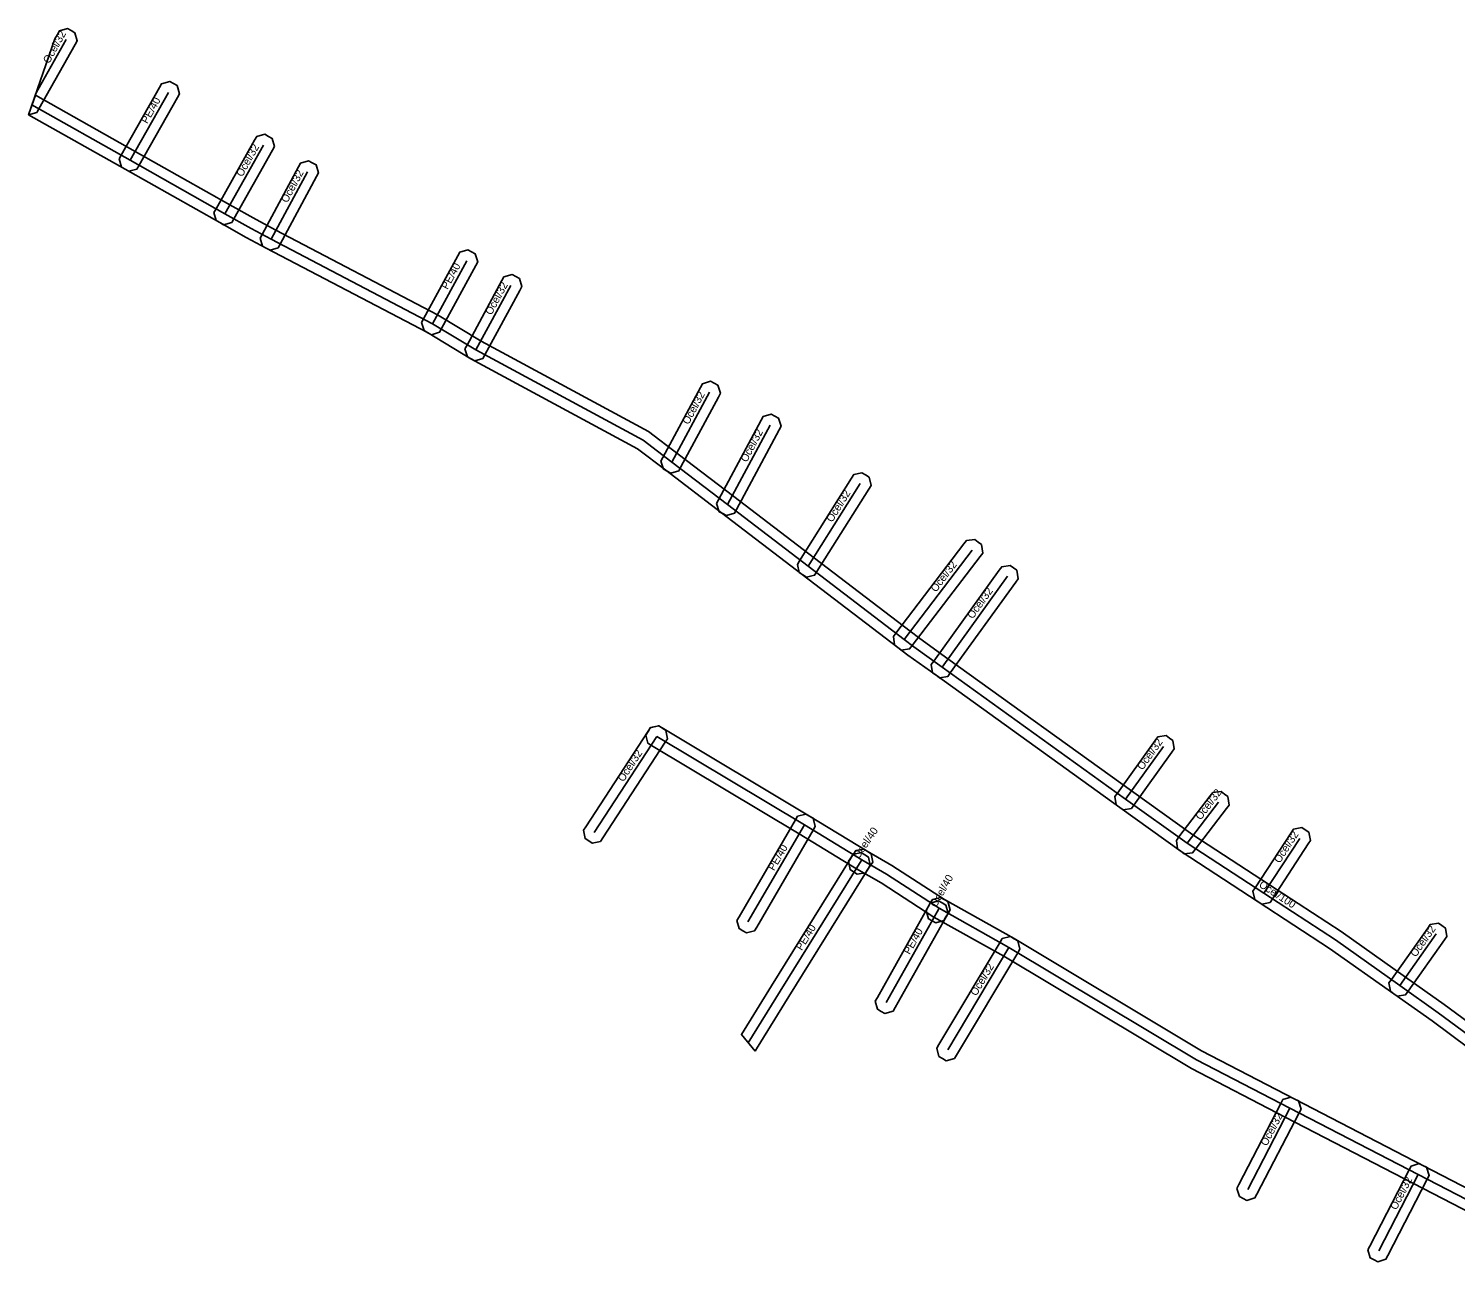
# Model space of a CAD drawing. Extents: x -588157 to -587884, y -1179022 to -1178805.
# Drawn here: x -588156.6 to -588016.9, y -1178925.9 to -1178805 of the extents above; entities that cross this region are included whole.
import ezdxf

# ---------------------------------------------------------------- set-up
doc = ezdxf.new("R2010")
doc.units = 0
for name, color, linetype in [('1', 7, 'Continuous'), ('14', 7, 'Continuous'), ('20', 7, 'Continuous')]:
    doc.layers.add(name, color=color, linetype=linetype)

msp = doc.modelspace()

# ---------------------------------------------------------------- linework, layer by layer
at = {"layer": '1'}
for points in [[(-588156.57, -1178813.424), (-588156.581, -1178813.418), (-588153.996, -1178805.976), (-588153.761, -1178805.559), (-588153.558, -1178805.198), (-588152.76, -1178804.976), (-588152.399, -1178805.179), (-588152.038, -1178805.382), (-588151.816, -1178806.18), (-588152.019, -1178806.541), (-588155.569, -1178812.841), (-588155.772, -1178813.202)], [(-588147.704, -1178817.75), (-588147.501, -1178817.389), (-588143.751, -1178810.739), (-588143.548, -1178810.378), (-588142.75, -1178810.156), (-588142.389, -1178810.359), (-588142.028, -1178810.562), (-588141.806, -1178811.36), (-588142.009, -1178811.721), (-588145.759, -1178818.371), (-588145.962, -1178818.732), (-588146.76, -1178818.954), (-588147.121, -1178818.751), (-588147.482, -1178818.548)], [(-588138.424, -1178822.98), (-588138.221, -1178822.619), (-588134.441, -1178815.919), (-588134.238, -1178815.558), (-588133.44, -1178815.336), (-588133.079, -1178815.539), (-588132.718, -1178815.742), (-588132.496, -1178816.54), (-588132.699, -1178816.901), (-588136.479, -1178823.601), (-588136.682, -1178823.962), (-588137.48, -1178824.184), (-588137.841, -1178823.981), (-588138.202, -1178823.778)], [(-588133.907, -1178825.501), (-588133.71, -1178825.136), (-588130.15, -1178818.526), (-588129.954, -1178818.161), (-588129.161, -1178817.923), (-588128.796, -1178818.12), (-588128.431, -1178818.316), (-588128.193, -1178819.109), (-588128.39, -1178819.474), (-588131.95, -1178826.084), (-588132.146, -1178826.449), (-588132.939, -1178826.687), (-588133.304, -1178826.49), (-588133.669, -1178826.294)], [(-588118.096, -1178833.768), (-588117.899, -1178833.404), (-588114.559, -1178827.234), (-588114.362, -1178826.87), (-588113.568, -1178826.634), (-588113.204, -1178826.831), (-588112.84, -1178827.028), (-588112.604, -1178827.822), (-588112.801, -1178828.186), (-588116.141, -1178834.356), (-588116.338, -1178834.72), (-588117.132, -1178834.956), (-588117.496, -1178834.759), (-588117.86, -1178834.562)], [(-588113.847, -1178836.338), (-588113.649, -1178835.973), (-588110.229, -1178829.663), (-588110.032, -1178829.299), (-588109.238, -1178829.063), (-588108.873, -1178829.261), (-588108.509, -1178829.458), (-588108.273, -1178830.252), (-588108.471, -1178830.617), (-588111.891, -1178836.927), (-588112.088, -1178837.291), (-588112.882, -1178837.527), (-588113.247, -1178837.329), (-588113.611, -1178837.132)], [(-588094.667, -1178847.333), (-588094.471, -1178846.968), (-588090.801, -1178840.118), (-588090.605, -1178839.753), (-588089.813, -1178839.513), (-588089.448, -1178839.709), (-588089.083, -1178839.905), (-588088.843, -1178840.697), (-588089.039, -1178841.062), (-588092.709, -1178847.912), (-588092.905, -1178848.277), (-588093.697, -1178848.517), (-588094.062, -1178848.321), (-588094.427, -1178848.125)], [(-588089.217, -1178851.494), (-588089.022, -1178851.129), (-588084.862, -1178843.339), (-588084.667, -1178842.974), (-588083.874, -1178842.733), (-588083.509, -1178842.928), (-588083.144, -1178843.123), (-588082.903, -1178843.916), (-588083.098, -1178844.281), (-588087.258, -1178852.071), (-588087.453, -1178852.436), (-588088.246, -1178852.677), (-588088.611, -1178852.482), (-588088.976, -1178852.287)], [(-588081.307, -1178857.449), (-588081.087, -1178857.098), (-588076.007, -1178849.008), (-588075.787, -1178848.657), (-588074.979, -1178848.473), (-588074.628, -1178848.693), (-588074.277, -1178848.913), (-588074.093, -1178849.721), (-588074.313, -1178850.072), (-588079.393, -1178858.162), (-588079.613, -1178858.513), (-588080.421, -1178858.697), (-588080.772, -1178858.477), (-588081.123, -1178858.257)], [(-588071.906, -1178864.513), (-588071.655, -1178864.183), (-588064.995, -1178855.453), (-588064.744, -1178855.124), (-588063.923, -1178855.014), (-588063.593, -1178855.265), (-588063.264, -1178855.516), (-588063.154, -1178856.337), (-588063.405, -1178856.667), (-588070.065, -1178865.397), (-588070.316, -1178865.726), (-588071.137, -1178865.836), (-588071.467, -1178865.585), (-588071.796, -1178865.334)], [(-588068.193, -1178867.252), (-588067.951, -1178866.916), (-588061.541, -1178858.016), (-588061.299, -1178857.68), (-588060.482, -1178857.547), (-588060.146, -1178857.789), (-588059.81, -1178858.031), (-588059.677, -1178858.848), (-588059.919, -1178859.184), (-588066.329, -1178868.084), (-588066.571, -1178868.42), (-588067.388, -1178868.553), (-588067.724, -1178868.311), (-588068.06, -1178868.069)], [(-588102.254, -1178883.49), (-588102.027, -1178883.143), (-588095.907, -1178873.773), (-588095.68, -1178873.426), (-588094.87, -1178873.256), (-588094.523, -1178873.483), (-588094.176, -1178873.71), (-588094.006, -1178874.52), (-588094.233, -1178874.867), (-588100.353, -1178884.237), (-588100.58, -1178884.584), (-588101.39, -1178884.754), (-588101.737, -1178884.527), (-588102.084, -1178884.3)], [(-588050.214, -1178880.182), (-588049.972, -1178879.846), (-588046.262, -1178874.686), (-588046.02, -1178874.35), (-588045.202, -1178874.216), (-588044.866, -1178874.458), (-588044.53, -1178874.7), (-588044.396, -1178875.518), (-588044.638, -1178875.854), (-588048.348, -1178881.014), (-588048.59, -1178881.35), (-588049.408, -1178881.484), (-588049.744, -1178881.242), (-588050.08, -1178881)], [(-588044.196, -1178884.472), (-588043.944, -1178884.143), (-588040.874, -1178880.127), (-588040.623, -1178879.798), (-588039.802, -1178879.688), (-588039.473, -1178879.94), (-588039.144, -1178880.191), (-588039.034, -1178881.012), (-588039.286, -1178881.341), (-588042.356, -1178885.357), (-588042.607, -1178885.686), (-588043.428, -1178885.796), (-588043.757, -1178885.544), (-588044.086, -1178885.293)], [(-588087.222, -1178892.315), (-588087.014, -1178891.957), (-588081.484, -1178882.467), (-588081.276, -1178882.109), (-588080.475, -1178881.898), (-588080.117, -1178882.106), (-588079.759, -1178882.314), (-588079.548, -1178883.115), (-588079.756, -1178883.473), (-588085.286, -1178892.963), (-588085.494, -1178893.321), (-588086.295, -1178893.532), (-588086.653, -1178893.324), (-588087.011, -1178893.116)], [(-588036.694, -1178889.461), (-588036.468, -1178889.114), (-588032.958, -1178883.734), (-588032.731, -1178883.387), (-588031.921, -1178883.216), (-588031.574, -1178883.442), (-588031.227, -1178883.669), (-588031.056, -1178884.479), (-588031.282, -1178884.826), (-588034.792, -1178890.206), (-588035.019, -1178890.553), (-588035.829, -1178890.724), (-588036.176, -1178890.498), (-588036.523, -1178890.271)], [(-588073.931, -1178886.614), (-588074.165, -1178886.956), (-588074.405, -1178887.306), (-588074.639, -1178887.647), (-588075.454, -1178887.799), (-588075.796, -1178887.565), (-588076.137, -1178887.331), (-588076.289, -1178886.516), (-588076.055, -1178886.174), (-588075.815, -1178885.824), (-588075.581, -1178885.483), (-588074.766, -1178885.331), (-588074.424, -1178885.565), (-588074.083, -1178885.799)], [(-588085.452, -1178905.119), (-588086.79, -1178903.484), (-588083.84, -1178898.723), (-588076.08, -1178886.213), (-588075.862, -1178885.861), (-588075.055, -1178885.672), (-588074.703, -1178885.89), (-588074.351, -1178886.108), (-588074.162, -1178886.915), (-588074.38, -1178887.267), (-588082.14, -1178899.777), (-588085.301, -1178904.878), (-588085.352, -1178904.96)], [(-588073.675, -1178900.221), (-588073.472, -1178899.86), (-588068.492, -1178890.99), (-588068.289, -1178890.629), (-588067.491, -1178890.405), (-588067.13, -1178890.608), (-588066.769, -1178890.811), (-588066.545, -1178891.609), (-588066.748, -1178891.97), (-588071.728, -1178900.84), (-588071.931, -1178901.201), (-588072.729, -1178901.425), (-588073.09, -1178901.222), (-588073.451, -1178901.019)], [(-588068.693, -1178891.344), (-588068.488, -1178890.984), (-588068.288, -1178890.634), (-588068.083, -1178890.274), (-588067.284, -1178890.057), (-588066.924, -1178890.262), (-588066.564, -1178890.467), (-588066.347, -1178891.266), (-588066.552, -1178891.626), (-588066.752, -1178891.976), (-588066.957, -1178892.336), (-588067.756, -1178892.553), (-588068.116, -1178892.348), (-588068.476, -1178892.143)], [(-588023.386, -1178898.441), (-588023.147, -1178898.103), (-588019.587, -1178893.063), (-588019.348, -1178892.725), (-588018.531, -1178892.584), (-588018.193, -1178892.823), (-588017.855, -1178893.062), (-588017.714, -1178893.879), (-588017.953, -1178894.217), (-588021.513, -1178899.257), (-588021.752, -1178899.595), (-588022.569, -1178899.736), (-588022.907, -1178899.497), (-588023.245, -1178899.258)], [(-588067.65, -1178904.822), (-588067.438, -1178904.467), (-588061.448, -1178894.447), (-588061.236, -1178894.092), (-588060.432, -1178893.89), (-588060.077, -1178894.102), (-588059.722, -1178894.314), (-588059.52, -1178895.118), (-588059.732, -1178895.473), (-588065.722, -1178905.493), (-588065.934, -1178905.848), (-588066.738, -1178906.05), (-588067.093, -1178905.838), (-588067.448, -1178905.626)], [(-588038.279, -1178918.557), (-588038.088, -1178918.189), (-588033.958, -1178910.229), (-588033.767, -1178909.862), (-588032.977, -1178909.611), (-588032.609, -1178909.802), (-588032.242, -1178909.993), (-588031.991, -1178910.783), (-588032.182, -1178911.151), (-588036.312, -1178919.111), (-588036.503, -1178919.478), (-588037.293, -1178919.729), (-588037.661, -1178919.538), (-588038.028, -1178919.347)], [(-588025.458, -1178924.569), (-588025.268, -1178924.201), (-588021.408, -1178916.731), (-588021.218, -1178916.363), (-588020.429, -1178916.112), (-588020.061, -1178916.302), (-588019.693, -1178916.492), (-588019.442, -1178917.281), (-588019.632, -1178917.649), (-588023.492, -1178925.119), (-588023.682, -1178925.487), (-588024.471, -1178925.738), (-588024.839, -1178925.548), (-588025.207, -1178925.358)]]:
    msp.add_lwpolyline(points, close=True, dxfattribs=at)
for points in [[(-588015.544, -1178904.832), (-588019.14, -1178902.163), (-588022.907, -1178899.497), (-588029.192, -1178895.057), (-588036.177, -1178890.497), (-588043.715, -1178885.575), (-588049.744, -1178881.242), (-588067.723, -1178868.312), (-588070.494, -1178866.324), (-588071.466, -1178865.585), (-588080.847, -1178858.425), (-588088.747, -1178852.395), (-588094.197, -1178848.235), (-588096.954, -1178846.133), (-588113.267, -1178837.318), (-588117.511, -1178834.752), (-588133.299, -1178826.493), (-588135.263, -1178825.436), (-588137.841, -1178823.981), (-588147.121, -1178818.751), (-588156.581, -1178813.418), (-588155.914, -1178811.499), (-588146.139, -1178817.009), (-588136.859, -1178822.239), (-588134.297, -1178823.684), (-588132.361, -1178824.727), (-588116.529, -1178833.008), (-588112.273, -1178835.582), (-588095.866, -1178844.447), (-588092.983, -1178846.645), (-588087.533, -1178850.805), (-588079.633, -1178856.835), (-588070.254, -1178863.995), (-588069.306, -1178864.716), (-588066.557, -1178866.688), (-588048.576, -1178879.618), (-588042.585, -1178883.925), (-588035.083, -1178888.823), (-588028.068, -1178893.403), (-588021.753, -1178897.863), (-588017.966, -1178900.543), (-588014.376, -1178903.208)], [(-588005.841, -1178925.907), (-588020.98, -1178918.078), (-588033.53, -1178911.578), (-588042.717, -1178906.824), (-588061.091, -1178895.825), (-588067.937, -1178891.987), (-588073.113, -1178888.633), (-588075.5, -1178887.25), (-588081.136, -1178883.826), (-588095.584, -1178875.178), (-588095.939, -1178874.965), (-588096.141, -1178874.161), (-588095.928, -1178873.806), (-588095.715, -1178873.451), (-588094.911, -1178873.249), (-588094.556, -1178873.462), (-588080.104, -1178882.114), (-588074.48, -1178885.53), (-588072.067, -1178886.927), (-588066.903, -1178890.273), (-588060.089, -1178894.095), (-588041.743, -1178905.076), (-588032.61, -1178909.802), (-588020.06, -1178916.302), (-588004.919, -1178924.133)]]:
    msp.add_lwpolyline(points, dxfattribs=at)
at = {"layer": '14'}
for points in [[(-588155.84, -1178811.286), (-588152.89, -1178806.05)], [(-588146.63, -1178817.88), (-588142.88, -1178811.23)], [(-588014.96, -1178904.02), (-588018.553, -1178901.353), (-588022.33, -1178898.68), (-588028.63, -1178894.23), (-588035.63, -1178889.66), (-588043.15, -1178884.75), (-588049.16, -1178880.43), (-588067.14, -1178867.5), (-588069.9, -1178865.52), (-588070.86, -1178864.79), (-588080.24, -1178857.63), (-588088.14, -1178851.6), (-588093.59, -1178847.44), (-588096.41, -1178845.29), (-588112.77, -1178836.45), (-588117.02, -1178833.88), (-588132.83, -1178825.61), (-588134.78, -1178824.56), (-588137.35, -1178823.11), (-588146.63, -1178817.88), (-588156.248, -1178812.458)], [(-588137.35, -1178823.11), (-588133.57, -1178816.41)], [(-588132.83, -1178825.61), (-588129.27, -1178819)], [(-588117.02, -1178833.88), (-588113.68, -1178827.71)], [(-588112.77, -1178836.45), (-588109.35, -1178830.14)], [(-588093.59, -1178847.44), (-588089.92, -1178840.59)], [(-588088.14, -1178851.6), (-588083.98, -1178843.81)], [(-588080.24, -1178857.63), (-588075.16, -1178849.54)], [(-588070.86, -1178864.79), (-588064.2, -1178856.06)], [(-588067.14, -1178867.5), (-588060.73, -1178858.6)], [(-588101.19, -1178883.69), (-588095.07, -1178874.32)], [(-588005.38, -1178925.02), (-588020.52, -1178917.19), (-588033.07, -1178910.69), (-588042.23, -1178905.95), (-588060.59, -1178894.96), (-588067.42, -1178891.13), (-588072.59, -1178887.78), (-588074.99, -1178886.39), (-588080.62, -1178882.97), (-588095.07, -1178874.32)], [(-588049.16, -1178880.43), (-588045.45, -1178875.27)], [(-588043.15, -1178884.75), (-588040.08, -1178880.734)], [(-588086.15, -1178892.46), (-588080.62, -1178882.97)], [(-588035.63, -1178889.66), (-588032.12, -1178884.28)], [(-588075.23, -1178886.74), (-588082.99, -1178899.25), (-588086.12, -1178904.302)], [(-588074.99, -1178886.39), (-588075.23, -1178886.74)], [(-588067.62, -1178891.48), (-588067.42, -1178891.13)], [(-588072.6, -1178900.35), (-588067.62, -1178891.48)], [(-588022.33, -1178898.68), (-588018.77, -1178893.64)], [(-588066.58, -1178904.98), (-588060.59, -1178894.96)], [(-588037.2, -1178918.65), (-588033.07, -1178910.69)], [(-588024.38, -1178924.66), (-588020.52, -1178917.19)]]:
    msp.add_lwpolyline(points, dxfattribs=at)

# ---------------------------------------------------------------- texts
at = {"layer": '20'}
for s, rotation, p in [('Ocel/32', 60.59909, (-588154.565, -1178808.468)), ('PE/40', 60.58092, (-588144.955, -1178814.355)), ('Ocel/32', 60.56922, (-588135.66, -1178819.56)), ('Ocel/32', 61.69408, (-588131.25, -1178822.105)), ('PE/40', 61.57203, (-588115.55, -1178830.595)), ('Ocel/32', 61.54245, (-588111.26, -1178833.095)), ('Ocel/32', 61.81909, (-588091.955, -1178843.815)), ('Ocel/32', 61.89698, (-588086.26, -1178847.505)), ('Ocel/32', 57.87382, (-588077.9, -1178853.385)), ('Ocel/32', 52.66048, (-588067.73, -1178860.225)), ('Ocel/32', 54.23763, (-588064.135, -1178862.85)), ('Ocel/32', 56.84951, (-588098.33, -1178878.805)), ('Ocel/32', 54.28416, (-588047.505, -1178877.65)), ('Ocel/32', 52.60418, (-588041.815, -1178882.542)), ('Ocel/40', 55.56101, (-588075.31, -1178886.365)), ('Ocel/32', 56.87891, (-588034.075, -1178886.77)), ('PE/40', 59.76985, (-588083.585, -1178887.515)), ('Ocel/40', 60.25512, (-588067.72, -1178891.105)), ('Ocel/100', 326.85845, (-588036.174, -1178888.974)), ('PE/40', 58.18852, (-588080.876, -1178895.32)), ('PE/40', 60.68827, (-588070.31, -1178895.715)), ('Ocel/32', 54.76456, (-588020.75, -1178895.96)), ('Ocel/32', 59.12883, (-588063.785, -1178899.77)), ('Ocel/32', 62.57772, (-588035.335, -1178914.47)), ('Ocel/32', 62.67308, (-588022.65, -1178920.725))]:
    msp.add_text(s, height=0.75, rotation=rotation, dxfattribs=at).set_placement(p)

doc.saveas('drawing.dxf')
